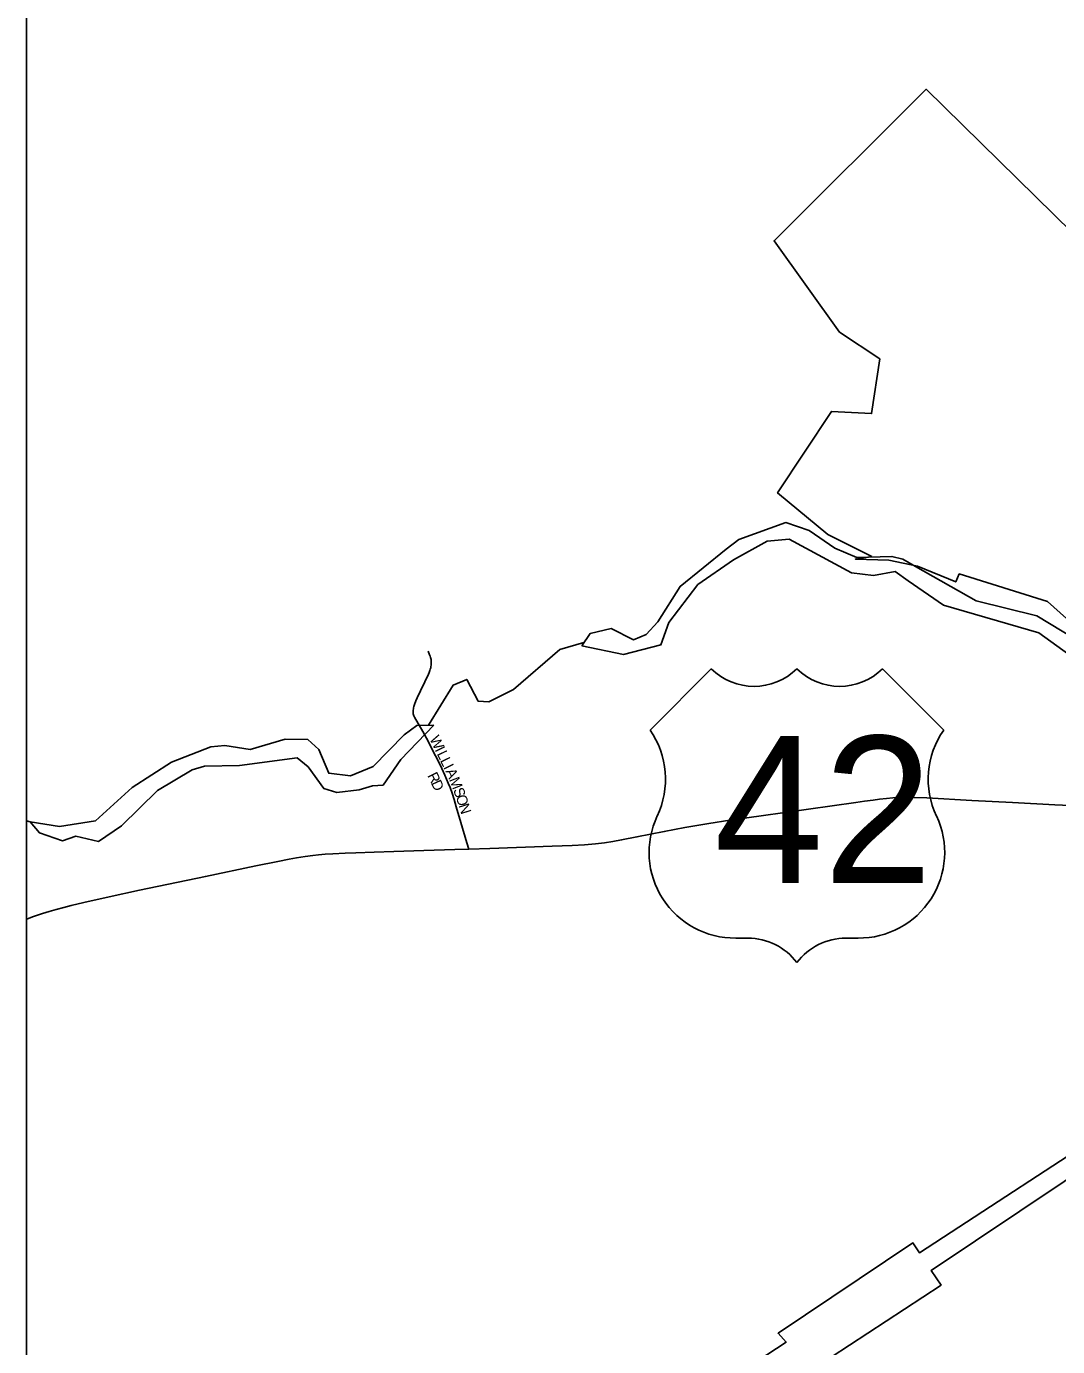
# Model space of a CAD drawing. Extents: x -49 to -8.2, y 9.4 to 23.5.
# Drawn here: x -14.966 to -14.503, y 15.202 to 15.795 of the extents above; entities that cross this region are included whole.
import ezdxf

# ---------------------------------------------------------------- set-up
doc = ezdxf.new("R2010")
doc.units = 0
for name, color, linetype in [('GM_X_Adjacent_County', 7, 'Continuous'), ('GM_X_Corporation', 7, 'Continuous'), ('GM_X_Minor_River', 7, 'Continuous'), ('GM_X_Township_Subdivision', 7, 'Continuous'), ('GM_X_Township_Subdivision_Text', 7, 'Continuous'), ('GM_X_US_Route', 7, 'Continuous'), ('GM_X_US_Shield', 7, 'Continuous')]:
    doc.layers.add(name, color=color, linetype=linetype)

msp = doc.modelspace()

# ---------------------------------------------------------------- linework, layer by layer
at = {"layer": 'GM_X_Adjacent_County'}
msp.add_lwpolyline([(-14.96621, 16.20866), (-8.16621, 16.20866), (-8.16621, 9.40866), (-14.96621, 9.40866)], close=True, dxfattribs=at)
at = {"layer": 'GM_X_Corporation'}
for points in [[(-14.43118, 15.63768), (-14.56232, 15.76636), (-14.63058, 15.6984), (-14.60114, 15.6573), (-14.58312, 15.64531), (-14.58677, 15.62081), (-14.60482, 15.62177), (-14.62902, 15.5852), (-14.60639, 15.56648), (-14.5867, 15.55663), (-14.59405, 15.55553), (-14.57909, 15.55502), (-14.56611, 15.55239), (-14.54899, 15.54527), (-14.54744, 15.54884), (-14.50782, 15.53649), (-14.48368, 15.51491)], [(-14.61316, 15.19186), (-14.55557, 15.22969), (-14.55997, 15.23626), (-14.24256, 15.44858), (-14.22303, 15.41987), (-14.2067, 15.43103), (-14.17452, 15.45301), (-14.1719, 15.44903), (-14.19558, 15.43174), (-14.18679, 15.41907), (-14.18485, 15.42117), (-14.17531, 15.42736), (-14.14955, 15.3917), (-14.14635, 15.4044), (-14.14614, 15.40433), (-14.14016, 15.39789), (-14.13613, 15.39353), (-14.1022, 15.42425), (-14.09584, 15.41685), (-14.12931, 15.38618), (-14.07776, 15.33058), (-14.04488, 15.36121), (-14.02933, 15.34272)], [(-14.38179, 15.36383), (-14.56523, 15.24413), (-14.56821, 15.24858), (-14.6288, 15.20804), (-14.62512, 15.20407), (-14.68455, 15.16511)]]:
    msp.add_lwpolyline(points, dxfattribs=at)
at = {"layer": 'GM_X_Minor_River'}
for points in [[(-14.71685, 15.51661), (-14.71315, 15.52206), (-14.70363, 15.52438), (-14.69365, 15.51928), (-14.68792, 15.52166), (-14.6827, 15.52727), (-14.67276, 15.54324), (-14.652, 15.56), (-14.64643, 15.56427), (-14.62523, 15.57191), (-14.61485, 15.56832), (-14.60322, 15.56035), (-14.59341, 15.55621), (-14.57765, 15.55671), (-14.57274, 15.5555), (-14.5671, 15.55218), (-14.53983, 15.53674), (-14.5126, 15.53004), (-14.49061, 15.51678)], [(-14.71685, 15.51661), (-14.69812, 15.51271), (-14.68135, 15.51699), (-14.67777, 15.527), (-14.66478, 15.54407), (-14.64885, 15.5552), (-14.63372, 15.5635), (-14.62384, 15.56448), (-14.5958, 15.54941), (-14.58595, 15.54812), (-14.57624, 15.54986), (-14.57043, 15.54578), (-14.55447, 15.53489), (-14.51178, 15.52243), (-14.48907, 15.50612)], [(-14.78576, 15.48095), (-14.77464, 15.49893), (-14.76852, 15.50149), (-14.76337, 15.49173), (-14.75863, 15.49146), (-14.74753, 15.49698), (-14.72674, 15.51487), (-14.7159, 15.51801)], [(-14.96446, 15.4376), (-14.96037, 15.4326), (-14.94999, 15.42902), (-14.94407, 15.43121), (-14.93386, 15.42876), (-14.9235, 15.43581), (-14.9073, 15.45169), (-14.89178, 15.46094), (-14.88625, 15.46256), (-14.87049, 15.46288), (-14.84463, 15.46626), (-14.83976, 15.4622), (-14.8327, 15.45259), (-14.82685, 15.45079), (-14.81677, 15.45196), (-14.81086, 15.45376), (-14.80611, 15.45407), (-14.79814, 15.46552), (-14.78328, 15.48104)], [(-14.96446, 15.4376), (-14.9514, 15.4355), (-14.93523, 15.43809), (-14.91867, 15.45301), (-14.90102, 15.46431), (-14.88345, 15.47124), (-14.87718, 15.4719), (-14.86582, 15.47001), (-14.84999, 15.4747), (-14.83994, 15.47454), (-14.83489, 15.47009), (-14.8305, 15.45939), (-14.82065, 15.45828), (-14.81053, 15.46249), (-14.79665, 15.47669), (-14.79099, 15.48077), (-14.78328, 15.48104)], [(-14.96621, 15.43806), (-14.96446, 15.4376)]]:
    msp.add_lwpolyline(points, dxfattribs=at)
at = {"layer": 'GM_X_Township_Subdivision'}
msp.add_lwpolyline([(-14.76764, 15.42533), (-14.7685, 15.42821), (-14.77122, 15.43731), (-14.77327, 15.44437), (-14.77422, 15.44766), (-14.77508, 15.45038), (-14.77599, 15.45292), (-14.77681, 15.45498), (-14.77755, 15.45674), (-14.77833, 15.45847), (-14.77977, 15.46159), (-14.78157, 15.46525), (-14.78359, 15.4692), (-14.78589, 15.4738), (-14.78823, 15.47816), (-14.79193, 15.48449), (-14.79213, 15.48484), (-14.79231, 15.48523), (-14.79244, 15.48562), (-14.79254, 15.48605), (-14.79258, 15.48642), (-14.7926, 15.48681), (-14.79258, 15.48726), (-14.79254, 15.48774), (-14.79248, 15.48831), (-14.7924, 15.48882), (-14.79227, 15.48932), (-14.79213, 15.48977), (-14.79194, 15.4903), (-14.79131, 15.49193), (-14.79074, 15.49328), (-14.7893, 15.49633), (-14.78733, 15.5004), (-14.78573, 15.5038), (-14.78539, 15.50465), (-14.78507, 15.50552), (-14.78489, 15.50609), (-14.78471, 15.50672), (-14.78458, 15.50734), (-14.7845, 15.50794), (-14.78444, 15.50855), (-14.78444, 15.50919), (-14.78448, 15.50974), (-14.78456, 15.51038), (-14.78465, 15.51089), (-14.78477, 15.51141), (-14.78495, 15.51196), (-14.78518, 15.51258), (-14.78584, 15.51414)], dxfattribs=at)
at = {"layer": 'GM_X_US_Route'}
msp.add_lwpolyline([(-14.96621, 15.39388), (-14.96603, 15.39395), (-14.96343, 15.39497), (-14.96126, 15.39576), (-14.959, 15.39649), (-14.95604, 15.3974), (-14.95288, 15.39827), (-14.94934, 15.39917), (-14.94607, 15.39998), (-14.94042, 15.40131), (-14.92912, 15.40387), (-14.91546, 15.40687), (-14.88582, 15.4131), (-14.86319, 15.41783), (-14.85327, 15.41983), (-14.84823, 15.42079), (-14.84502, 15.42136), (-14.84102, 15.422), (-14.83762, 15.42245), (-14.83504, 15.42272), (-14.83205, 15.42302), (-14.82864, 15.42324), (-14.82305, 15.4235), (-14.81839, 15.42367), (-14.81002, 15.42395), (-14.80133, 15.42426), (-14.78782, 15.42465), (-14.77388, 15.4251), (-14.76764, 15.42533), (-14.75814, 15.42568), (-14.73023, 15.42667), (-14.72127, 15.427), (-14.71568, 15.42733), (-14.71075, 15.42774), (-14.70672, 15.42823), (-14.70298, 15.42876), (-14.699, 15.4295), (-14.69213, 15.43082), (-14.67984, 15.4332), (-14.67055, 15.43501), (-14.65987, 15.43678), (-14.65038, 15.43826), (-14.63636, 15.44031), (-14.61509, 15.44328), (-14.59387, 15.44629), (-14.59004, 15.44685), (-14.58601, 15.44738), (-14.58325, 15.44775), (-14.58005, 15.44808), (-14.57722, 15.44833), (-14.57471, 15.44849), (-14.57125, 15.44862), (-14.56785, 15.44857), (-14.56194, 15.44836), (-14.54177, 15.44723), (-14.52347, 15.44623), (-14.50456, 15.44523), (-14.48718, 15.44448)], dxfattribs=at)
at = {"layer": 'GM_X_US_Shield'}
for p, q in [((-14.65878, 15.50625), (-14.68624, 15.47878)), ((-14.55441, 15.47878), (-14.58187, 15.50625)), ((-14.64779, 15.3854), (-14.6423, 15.3854)), ((-14.59835, 15.3854), (-14.59286, 15.3854))]:
    msp.add_line(p, q, dxfattribs=at)
for centre, radius, start, end in [((-14.63955, 15.52586), 0.02747, 225.573, 314.427), ((-14.6011, 15.52586), 0.02747, 225.573, 314.427), ((-14.71774, 15.45672), 0.03845, 334.54712, 35.00093), ((-14.52291, 15.45672), 0.03845, 144.99907, 205.45288), ((-14.64822, 15.42385), 0.03845, 154.83192, 270.63826), ((-14.59243, 15.42385), 0.03845, 269.36174, 25.16808), ((-14.6423, 15.35793), 0.02747, 36.8699, 90), ((-14.59835, 15.35793), 0.02747, 90, 143.1301)]:
    msp.add_arc(centre, radius, start, end, dxfattribs=at)

# ---------------------------------------------------------------- texts
at = {"layer": 'GM_X_Township_Subdivision_Text'}
for s, rotation, p in [('W', 296.00114, (-14.78536, 15.47487)), ('I', 296.01098, (-14.78298, 15.47)), ('L', 295.99078, (-14.78207, 15.46813)), ('L', 295.99972, (-14.78061, 15.46513)), ('R', 296.40213, (-14.78632, 15.45836)), ('I', 296.01098, (-14.77915, 15.46214)), ('A', 294.95221, (-14.77824, 15.46029)), ('D', 294.57059, (-14.78467, 15.45503)), ('M', 291.42594, (-14.77652, 15.45658)), ('S', 290.48252, (-14.7747, 15.45194)), ('O', 288.45569, (-14.77354, 15.44886)), ('N', 287.56397, (-14.77223, 15.44493))]:
    msp.add_text(s, height=0.00473, rotation=rotation, dxfattribs=at).set_placement(p)
at = {"layer": 'GM_X_US_Shield'}
msp.add_text('42', height=0.065918, dxfattribs=at).set_placement((-14.65743, 15.41012))

doc.saveas('drawing.dxf')
